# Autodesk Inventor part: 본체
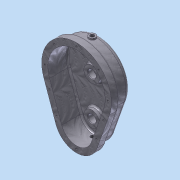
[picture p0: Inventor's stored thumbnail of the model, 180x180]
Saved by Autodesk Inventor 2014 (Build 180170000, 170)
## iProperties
Created: 2024-05
Part Number: 본체
Material: 알루미늄 6061, 용접
Document SubType Name: Modeling
Designer: dg
Density: 2.71 g/cm^3
Appearance: 용접 - 알루미늄
Mass: 506.304 g
Surface Area: 652.283 cm^2
Volume: 186.828 cm^3
Author: dg
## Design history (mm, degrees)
sketch "스케치1"
  geometry: L1 (-58.454, 14.548)-(-36.77, -46.785); L2 (0, 97.215)-(0, -72.785); L3 (58.454, 14.548)-(36.77, -46.785); A1 r 62 centre (0, 35.215) between (58.454, 14.548) and (-58.454, 14.548); A2 r 39 centre (0, -33.785) between (-36.77, -46.785) and (36.77, -46.785); 1 further point
  constraints: 6 end point, 6 point on circle, 2 centre point, 2 symmetric about line, 2 tangent, 2 vertical alignment, 1 vertical
  dimensions: "d0" = 124 diameter of A1; "d2" = 69 distance of A2.centre A1.centre; "d3" = 39 radius of A2
extrude "돌출1" new body sketch "스케치1" distance "d4" = 15; taper "d5" = 0 deg
sketch "스케치2"
  geometry: L1 (-36.77, 46.785)-(-58.454, -14.548) reference; L2 (-31.113, 44.785)-(-53.682, -19.052); L3 (0, 72.785)-(0, -97.215); L4 (31.113, 44.785)-(53.682, -19.052); A1 r 39 centre (0, 33.785) between (36.77, 46.785) and (-36.77, 46.785) reference; A2 r 62 centre (0, -35.215) between (-58.454, -14.548) and (58.454, -14.548) reference; A3 r 56 centre (0, -35.215) between (-52.797, -16.548) and (52.797, -16.548); A4 r 33 centre (0, 33.785) between (31.113, 44.785) and (-31.113, 44.785); 1 further point
  constraints: 6 end point, 6 point on circle, 2 centre point, 2 coincident, 2 point on line, 2 symmetric about line, 2 tangent, 1 parallel
  dimensions: "d6" = 112 diameter of A3; "d7" = 66 diameter of A4
extrude "돌출2" join sketch "스케치2" distance "d8" = 25; taper "d9" = 0 deg
feature "쉘1" dims "d10" = 5
sketch "스케치3"
  geometry: L1 (26.399, -78.333)-(48.083, -17) reference; L2 (53.74, -19)-(32.056, -80.333) reference; L3 (-32.056, -80.333)-(-53.74, -19) reference; L4 (53.74, -19)-(32.056, -80.333) reference; L5 (-48.083, -17)-(-26.399, -78.333); L6 (48.083, -17)-(26.399, -78.333); L7 (48.083, -17)-(26.399, -78.333) reference; L8 (53.74, -19)-(32.056, -80.333); L9 (58.454, -20.667)-(36.77, -82) reference; L10 (-53.74, -19)-(-32.056, -80.333); A1 r 28 centre (0, -69) between (-26.399, -78.333) and (26.399, -78.333) reference; A2 r 51 centre (0, 0) between (48.083, -17) and (-48.083, -17) reference; A3 r 57 centre (0, 0) between (53.74, -19) and (-53.74, -19) reference; A4 r 34 centre (0, -69) between (-32.056, -80.333) and (32.056, -80.333) reference; A5 r 57 centre (0, 0) between (53.74, -19) and (-53.74, -19) reference; A6 r 34 centre (0, -69) between (-32.056, -80.333) and (32.056, -80.333) reference; A7 r 28 centre (0, -69) between (-26.399, -78.333) and (26.399, -78.333); A8 r 57 centre (0, 0) between (53.74, -19) and (-53.74, -19); A9 r 34 centre (0, -69) between (-32.056, -80.333) and (32.056, -80.333); A10 r 51 centre (0, 0) between (48.083, -17) and (-48.083, -17); 1 further point
  constraints: 20 tangent, 10 end point, 9 point on circle, 4 centre point, 4 coincident, 4 equal length, 3 point on line
extrude "돌출3" join sketch "스케치3" stored distance "d11" = 25; taper "d12" = 0 deg
sketch "스케치4"
  geometry: A1 r 51 centre (0, 35.215) between (48.083, 18.215) and (-48.083, 18.215) reference; 2 further points
  constraints: 1 vertical alignment
  dimensions: "d13" = 56 distance of A1.centre point (0, 91.215)
hole "구멍1" sketch "스케치4" at (0, 91.215) diameter "d14" = 3.242; stored, may be unused: countersink angle "d18" = 90 deg, drill point angle "d20" = 118 deg; dims "d15" = 8, "d16" = 4, "d17" = 2, "d19" = 10
sketch "스케치5"
  geometry: L1 (-36.77, -46.785)-(-58.454, 14.548) reference; L2 (-52.797, 16.548)-(-31.113, -44.785) reference; C1 r 1.621 at (-56, 35.215) reference; A1 r 33 centre (0, -33.785) between (-31.113, -44.785) and (31.113, -44.785) reference; 2 further points
  dimensions: "d24" = 69 vertical distance of point (-35.532, -33.785) C1.centre; "d25" = 5.5 distance from line of L1 point (-35.532, -33.785)
hole "구멍2" sketch "스케치5" at (-35.532, -33.785) diameter "d26" = 3.242; stored, may be unused: countersink angle "d30" = 90 deg, drill point angle "d32" = 118 deg; dims "d27" = 8, "d28" = 4, "d29" = 2, "d31" = 10
sketch "스케치6"
  geometry: L1 (-48.083, 18.215)-(-26.399, -43.118) reference; C1 r 1.621 at (-56, 35.215) reference; 3 further points
  dimensions: "d33" = 34 vertical distance of C1.centre point (-47.906, 1.215); "d34" = 5.5 distance from line of L1 point (-47.906, 1.215)
hole "구멍3" sketch "스케치6" at (-47.906, 1.215) diameter "d35" = 3.242; stored, may be unused: countersink angle "d39" = 90 deg, drill point angle "d41" = 118 deg; dims "d36" = 8, "d37" = 4, "d38" = 2, "d40" = 10
sketch "스케치7"
  geometry: A1 r 39 centre (0, -33.785) between (-36.77, -46.785) and (36.77, -46.785) reference; 2 further points
  constraints: 1 vertical alignment
  dimensions: "d42" = 33 distance of A1.centre point (0, -66.785)
hole "구멍4" sketch "스케치7" at (0, -66.785) diameter "d43" = 3.242; stored, may be unused: countersink angle "d47" = 90 deg, drill point angle "d49" = 118 deg; dims "d44" = 8, "d45" = 4, "d46" = 2, "d48" = 10
sketch "스케치8"
  geometry: C1 r 14 at (0, 0); A1 r 51 centre (0, 0) between (48.083, -17) and (-48.083, -17) reference; 1 further point
  constraints: 1 centre point, 1 coincident
  dimensions: "d50" = 28 diameter of C1
extrude "돌출4" join sketch "스케치8" distance "d51" = 8; taper "d52" = 0 deg
sketch "스케치9"
  geometry: C1 r 15 at (0, -35.215); A1 r 56 centre (0, -35.215) between (-52.797, -16.548) and (52.797, -16.548) reference; 1 further point
  constraints: 1 centre point, 1 coincident
  dimensions: "d53" = 30 diameter of C1
extrude "돌출5" join sketch "스케치9" distance "d54" = 8; taper "d55" = 0 deg
sketch "스케치10"
  geometry: C1 r 14 at (0, -69); A1 r 28 centre (0, -69) between (-26.399, -78.333) and (26.399, -78.333) reference; 1 further point
  constraints: 1 centre point, 1 coincident
  dimensions: "d57" = 28 diameter of C1
extrude "돌출6" join sketch "스케치10" distance "d58" = 8; taper "d59" = 0 deg
sketch "스케치11"
  geometry: C1 r 14 at (0, 33.785) reference; C2 r 15 at (0, 33.785); 1 further point
  constraints: 1 centre point, 1 coincident
  dimensions: "d60" = 30 diameter of C2
extrude "돌출7" join sketch "스케치11" distance "d61" = 8; taper "d62" = 0 deg
hole "구멍5" diameter "d65" = 8; stored, may be unused: countersink angle "d69" = 90 deg, drill point angle "d71" = 120 deg; dims "d63" = 10, "d64" = 10, "d66" = 8, "d67" = 4, "d68" = 2, "d70" = 10
sketch "스케치12"
  geometry: C1 r 4 at (0, 0) reference; C2 r 14 at (0, 0) reference; C3 r 7 at (0, 0); 1 further point
  constraints: 1 centre point, 1 coincident
  dimensions: "d72" = 14 diameter of C3
extrude "돌출8" cut sketch "스케치12" distance "d73" = 10; taper "d74" = 0 deg
hole "구멍6" diameter "d77" = 14; stored, may be unused: countersink angle "d81" = 90 deg, drill point angle "d83" = 120 deg; dims "d75" = 10, "d76" = 10, "d78" = 8, "d79" = 20, "d80" = 4.2, "d82" = 10
chamfer "모따기1" distance "d84" = 1; stored, may be unused: second distance "d85" = 2, angle "d86" = 45 deg
chamfer "모따기2" distance "d87" = 0.1; stored, may be unused: second distance "d88" = 2, angle "d89" = 45 deg
chamfer "모따기3" distance "d90" = 0.4; stored, may be unused: second distance "d91" = 2, angle "d92" = 45 deg
fillet "모깎기1" dims "d93" = 3, "d94" = 8
fillet "모깎기2" dims "d95" = 3
node "작업 평면2"
node "작업 평면3"
sketch "스케치13"
  geometry: L1 (62, 0)-(-62, 0) reference; C1 r 6 at (0, 28); 4 further points
  constraints: 1 centre point, 1 midpoint, 1 vertical alignment
  dimensions: "d98" = 28 distance from line of C1.centre L1; "d99" = 12 diameter of C1
extrude "돌출9" join sketch "스케치13" stored distance "d100" = 10; taper "d101" = 0 deg
sketch "스케치14"
  geometry: C1 r 6 at (0, 28) reference; C2 r 6 at (0, 28); 1 further point
  constraints: 1 centre point, 1 coincident, 1 concentric
extrude "돌출10" join sketch "스케치14" stored distance "d102" = 10; taper "d103" = 0 deg
hole "구멍7" diameter "d106" = 6.188; stored, may be unused: countersink angle "d110" = 90 deg, drill point angle "d112" = 118 deg; dims "d107" = 20, "d108" = 7, "d109" = 2, "d111" = 8, "d126" = 10, "d127" = 10
hole "구멍8" diameter "d115" = 6.188; stored, may be unused: countersink angle "d119" = 90 deg, drill point angle "d121" = 118 deg; dims "d116" = 20, "d117" = 7, "d118" = 2, "d120" = 8, "d124" = 10, "d125" = 10
sketch "스케치15"
  geometry: C1 r 18 at (0, -35.215) reference; 2 further points
  constraints: 1 vertical alignment, 1 other
  dimensions: "d122" = 30 distance of C1.centre point (0, -65.215)
extrude "돌출11" join sketch "스케치15" distance "d123" = 0.5; taper "d128" = 0 deg
node "솔리드1"
pattern_circular "원형 패턴1" dims angle "d22" = 360 deg
mirror "대칭1"
node "투영된 루프1"
other parameters: "d1" = 78, "d96" = 94, "d97" = -71
